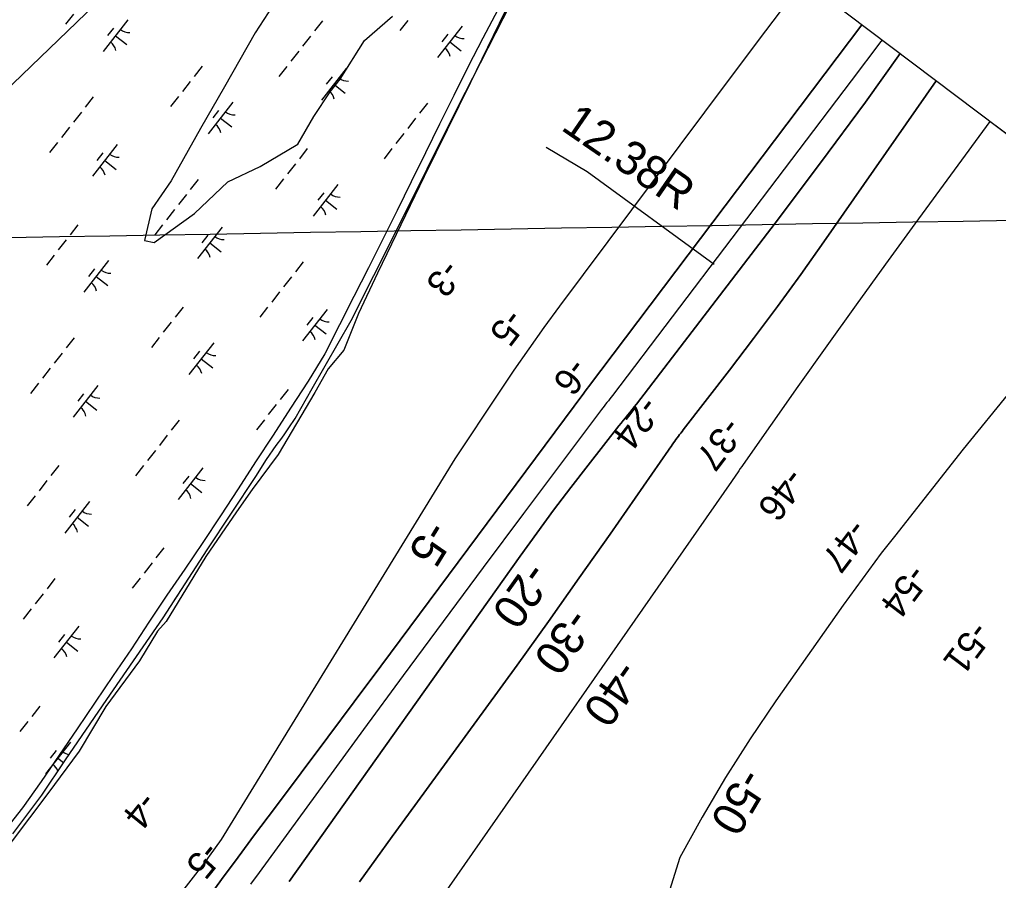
# Model space of a CAD drawing. Extents: x 3896831 to 3918110, y 171006 to 193349.
# Drawn here: x 3911133 to 3912353, y 186461 to 187534 of the extents above; entities that cross this region are included whole.
import ezdxf

# ---------------------------------------------------------------- set-up
doc = ezdxf.new("R2010")
doc.units = 0
for name, color, linetype in [('V-GRID-FRAM', 7, 'Continuous'), ('V-GRID-MAJR', 7, 'Continuous'), ('V-LEVE-TOET', 7, 'Continuous'), ('V-RIVR-EDGE', 7, 'Continuous'), ('V-RIVR-RANG', 7, 'Continuous'), ('V-RRAP-FSHR', 7, 'Continuous'), ('V-STRM-FMON', 7, 'Continuous'), ('V-TOPO-DPTH', 7, 'Continuous'), ('V-TOPO-MAJR', 7, 'Continuous'), ('V-TOPO-MAJR-IDEN', 7, 'Continuous'), ('V-TOPO-MINR', 7, 'Continuous'), ('V-TOPO-MINR-IDEN', 7, 'Continuous'), ('V-TOPO-SHOR', 7, 'Continuous'), ('V-UTIL-LINE', 7, 'Continuous'), ('V-WETL-SWMP', 7, 'Continuous')]:
    doc.layers.add(name, color=color, linetype=linetype)

msp = doc.modelspace()

# ---------------------------------------------------------------- linework, layer by layer
at = {"layer": 'V-GRID-FRAM'}
msp.add_lwpolyline([(3916044.9, 184610), (3906752.8, 172754.1), (3900055.1, 177809.8), (3909313.3, 189695.8), (3916044.9, 184610)], dxfattribs=at)
at = {"layer": 'V-GRID-MAJR'}
msp.add_spline([(3906725.4, 187187.1), (3909556.5, 187235.6), (3913560.3, 187304.5)], degree=3, dxfattribs=at)
at = {"layer": 'V-LEVE-TOET'}
msp.add_lwpolyline([(3911789.5, 187374.9), (3911840.5, 187344.6), (3911998.7, 187229.4)], dxfattribs=at)
at = {"layer": 'V-RIVR-EDGE'}
msp.add_lwpolyline([(3911759.3, 187587.7), (3911695.2, 187455.7), (3911637.6, 187338.7), (3911579.1, 187217.9), (3911555.8, 187167.7), (3911537.3, 187122.2), (3911517.7, 187098.9), (3911501, 187069.2), (3911455.5, 186992.1), (3911423, 186948.4), (3911403.4, 186920.5), (3911365.3, 186864.8), (3911316.1, 186783.9), (3911304.9, 186771.8), (3911282.6, 186734.7), (3911240.8, 186678), (3911207.4, 186622.2), (3911168.4, 186569.3), (3911100.5, 186480.1)], dxfattribs=at)
at = {"layer": 'V-RRAP-FSHR'}
msp.add_lwpolyline([(3911729.1, 187546.3), (3911710.6, 187510.8), (3911692.2, 187475.4), (3911674.3, 187439.6), (3911656.6, 187403.7), (3911639.2, 187367.8), (3911621.4, 187331.9), (3911603.7, 187296), (3911585.9, 187260.2), (3911567.9, 187224.5), (3911549.8, 187188.8), (3911531.8, 187153.5), (3911513.8, 187117.3), (3911492.8, 187083.4), (3911471, 187049.8), (3911449.1, 187016.3), (3911427.3, 186982.8), (3911405.5, 186949.3), (3911383.7, 186915.7), (3911361.6, 186882.4), (3911339.2, 186849.2), (3911316.9, 186816.7), (3911294.5, 186782.9), (3911272.8, 186749.8), (3911249.7, 186716.6), (3911227.3, 186683.5), (3911204.9, 186650.3), (3911182.5, 186617.2), (3911160.1, 186584.5), (3911136.7, 186551.6), (3911112.2, 186520.5)], dxfattribs=at)
at = {"layer": 'V-TOPO-DPTH'}
msp.add_line((3913012.1, 186901.3), (3912342.5, 187407.2), dxfattribs=at)
for points in [[(3910975.3, 185824.5), (3910982.9, 185836.6), (3910990.4, 185848.6), (3910997.8, 185860.8), (3911005, 185873.1), (3911012, 185885.5), (3911344.1, 186406.2), (3911364.5, 186434.2), (3911384.9, 186462.3), (3911405.5, 186490.2), (3911426.2, 186518), (3911451, 186551), (3911484.1, 186595.3), (3911517.2, 186639.6), (3911550.2, 186683.9), (3911583.3, 186728.3), (3911836.5, 187068.6), (3911837.2, 187069.6), (3911839.4, 187072.5), (3911840.9, 187074.5), (3911842.4, 187076.4), (3912183.1, 187527.7)], [(3912230.8, 187491.6), (3912187.4, 187431), (3912131.5, 187355.5), (3912074.9, 187280.4), (3911901.9, 187054.8), (3911899.2, 187051.3), (3911896.5, 187047.9), (3911893.8, 187044.5), (3911891, 187041.1), (3911888.3, 187037.8), (3911885.6, 187034.4), (3911882.8, 187031), (3911880.2, 187027.6), (3911841.8, 186978.7), (3911820.2, 186950.8), (3911798.8, 186922.6), (3911777.8, 186894.1), (3911757.1, 186865.4), (3911469, 186459.8)], [(3911469, 186459.8), (3911757.1, 186865.4), (3911777.8, 186894.1), (3911798.8, 186922.6), (3911820.2, 186950.8), (3911841.8, 186978.7), (3911880.2, 187027.6), (3911882.8, 187031), (3911885.6, 187034.4), (3911888.3, 187037.8), (3911891, 187041.1), (3911893.8, 187044.5), (3911896.5, 187047.9), (3911899.2, 187051.3), (3911901.9, 187054.8), (3912074.9, 187280.4), (3912131.5, 187355.5), (3912187.4, 187431), (3912230.8, 187491.6)], [(3912275.5, 187457.9), (3912135.5, 187256.9), (3912106.8, 187216.4), (3912077.8, 187176.3), (3912048.1, 187136.6), (3912018.1, 187097.2), (3911960.4, 187022.8), (3911958.9, 187020.8), (3911957.4, 187018.8), (3911955.8, 187016.8), (3911954.3, 187014.8), (3911952.8, 187012.8), (3911951.3, 187010.8), (3911949.9, 187008.7), (3911948.4, 187006.6), (3911946.7, 187004.1), (3911945.2, 187001.9), (3911943.7, 186999.7), (3911942.1, 186997.5), (3911869.1, 186892.6), (3911830.8, 186838.1), (3911792.3, 186783.7), (3911753.5, 186729.6), (3911714.4, 186675.7), (3911617.9, 186543.8), (3911597.5, 186515.7), (3911577.1, 186487.5), (3911556.9, 186459.2)], [(3911556.9, 186459.2), (3911577.1, 186487.5), (3911597.5, 186515.7), (3911617.9, 186543.8), (3911714.4, 186675.7), (3911753.5, 186729.6), (3911792.3, 186783.7), (3911830.8, 186838.1), (3911869.1, 186892.6), (3911942.1, 186997.5), (3911943.7, 186999.7), (3911945.2, 187001.9), (3911946.7, 187004.1), (3911948.4, 187006.6), (3911949.9, 187008.7), (3911951.3, 187010.8), (3911952.8, 187012.8), (3911954.3, 187014.8), (3911955.8, 187016.8), (3911957.4, 187018.8), (3911958.9, 187020.8), (3911960.4, 187022.8), (3912018.1, 187097.2), (3912048.1, 187136.6), (3912077.8, 187176.3), (3912106.8, 187216.4), (3912135.5, 187256.9), (3912275.5, 187457.9)], [(3912342.5, 187407.2), (3912249.1, 187279.6), (3912212.3, 187229.1), (3912175.7, 187178.4), (3912139.4, 187127.6), (3912103.3, 187076.6), (3912035.2, 186979.7), (3912033.3, 186977.1), (3912031.5, 186974.4), (3912029.6, 186971.7), (3912027.8, 186969), (3912025.9, 186966.3), (3912024.1, 186963.6), (3912022.2, 186960.9), (3912020.4, 186958.3), (3911636.9, 186408.5)], [(3912342.5, 187407.2), (3912249.1, 187279.6), (3912212.3, 187229.1), (3912175.7, 187178.4), (3912139.4, 187127.6), (3912103.3, 187076.6), (3912035.2, 186979.7), (3912033.3, 186977.1), (3912031.5, 186974.4), (3912029.6, 186971.7), (3912027.8, 186969), (3912025.9, 186966.3), (3912024.1, 186963.6), (3912022.2, 186960.9), (3912020.4, 186958.3), (3911636.9, 186408.5)]]:
    msp.add_lwpolyline(points, dxfattribs=at)
at = {"layer": 'V-TOPO-MAJR'}
msp.add_lwpolyline([(3912369.6, 187072.8), (3912309.2, 186998.5), (3912223.6, 186890), (3912207.2, 186868.9), (3912191.1, 186847.5), (3912175.3, 186825.9), (3912159.7, 186804.2), (3912075.9, 186684.9), (3912043.8, 186637.5), (3912013, 186589.3), (3911983.9, 186539.9), (3911956.1, 186489.8), (3911903.8, 186322.5)], dxfattribs=at)
at = {"layer": 'V-TOPO-MINR'}
for points in [[(3912110.3, 187582.7), (3912109.9, 187582.2), (3912063, 187520.2), (3912016.3, 187458.1), (3911806, 187176.9), (3911786.7, 187150.5), (3911767.7, 187123.9), (3911749.1, 187097), (3911730.8, 187069.9), (3911675.8, 186986.6), (3911384.6, 186512.1), (3911369.5, 186491.3), (3911368.2, 186489.6), (3911365.6, 186486.1), (3911364.3, 186484.4), (3911362.3, 186481.8), (3911361, 186480), (3910921.7, 185915.3), (3910911.1, 185901.5), (3910900.5, 185887.7), (3910890, 185873.8), (3910879.6, 185859.8), (3910869.3, 185845.7), (3910859.2, 185831.5)], [(3912183.1, 187527.7), (3911842.4, 187076.4), (3911840.9, 187074.5), (3911839.4, 187072.5), (3911837.2, 187069.6), (3911836.5, 187068.6), (3911583.3, 186728.3), (3911550.2, 186683.9), (3911517.2, 186639.6), (3911484.1, 186595.3), (3911451, 186551), (3911426.2, 186518), (3911405.5, 186490.2), (3911384.9, 186462.3), (3911364.5, 186434.2), (3911344.1, 186406.2), (3911012, 185885.5), (3911005, 185873.1), (3910997.8, 185860.8), (3910990.4, 185848.6), (3910982.9, 185836.6), (3910975.3, 185824.5)], [(3912208.1, 187508.8), (3912206.6, 187506.8), (3912169.7, 187457.6), (3911872.1, 187065.6), (3911870.4, 187063.4), (3911868.7, 187061.2), (3911867, 187059), (3911865.3, 187056.8), (3911863.6, 187054.6), (3911861.9, 187052.4), (3911860.2, 187050.1), (3911858.5, 187047.9), (3911761.3, 186918.4), (3911711.1, 186851.3), (3911661.1, 186784), (3911611.4, 186716.6), (3911561.9, 186649.1), (3911431.8, 186471.1), (3911421.2, 186456.4)], [(3912230.8, 187491.6), (3912187.4, 187431), (3912131.5, 187355.5), (3912074.9, 187280.4), (3911901.9, 187054.8), (3911899.2, 187051.3), (3911896.5, 187047.9), (3911893.8, 187044.5), (3911891, 187041.1), (3911888.3, 187037.8), (3911885.6, 187034.4), (3911882.8, 187031), (3911880.2, 187027.6), (3911841.8, 186978.7), (3911820.2, 186950.8), (3911798.8, 186922.6), (3911777.8, 186894.1), (3911757.1, 186865.4), (3911469, 186459.8)], [(3912275.5, 187457.9), (3912135.5, 187256.9), (3912106.8, 187216.4), (3912077.8, 187176.3), (3912048.1, 187136.6), (3912018.1, 187097.2), (3911960.4, 187022.8), (3911958.9, 187020.8), (3911957.4, 187018.8), (3911955.8, 187016.8), (3911954.3, 187014.8), (3911952.8, 187012.8), (3911951.3, 187010.8), (3911949.9, 187008.7), (3911948.4, 187006.6), (3911946.7, 187004.1), (3911945.2, 187001.9), (3911943.7, 186999.7), (3911942.1, 186997.5), (3911869.1, 186892.6), (3911830.8, 186838.1), (3911792.3, 186783.7), (3911753.5, 186729.6), (3911714.4, 186675.7), (3911617.9, 186543.8), (3911597.5, 186515.7), (3911577.1, 186487.5), (3911556.9, 186459.2)], [(3912342.5, 187407.2), (3912249.1, 187279.6), (3912212.3, 187229.1), (3912175.7, 187178.4), (3912139.4, 187127.6), (3912103.3, 187076.6), (3912035.2, 186979.7), (3912033.3, 186977.1), (3912031.5, 186974.4), (3912029.6, 186971.7), (3912027.8, 186969), (3912025.9, 186966.3), (3912024.1, 186963.6), (3912022.2, 186960.9), (3912020.4, 186958.3), (3911636.9, 186408.5)]]:
    msp.add_lwpolyline(points, dxfattribs=at)
at = {"layer": 'V-TOPO-SHOR'}
msp.add_lwpolyline([(3911459.1, 187567.9), (3911426.8, 187517.6), (3911388.6, 187450.4), (3911358.6, 187398.3), (3911322.1, 187333.3), (3911298.1, 187298.2), (3911288.7, 187258.7), (3911301.1, 187256.2), (3911351.2, 187292.5), (3911392.9, 187331.8), (3911432.9, 187350.8), (3911480, 187378.7), (3911500, 187413.4), (3911520.5, 187444.2), (3911532.7, 187459.8), (3911563.2, 187507.9), (3911597.9, 187538.3)], dxfattribs=at)
at = {"layer": 'V-UTIL-LINE'}
msp.add_lwpolyline([(3911670.5, 187980.3), (3909726.1, 186106.6), (3909690.7, 186047.7), (3909490.4, 185423.1), (3908571.2, 184256.5), (3908123.4, 183643.7), (3907157.1, 182394.6), (3906544.4, 181593.3), (3906120.1, 181051.2), (3905460.2, 180002.4), (3904670.7, 178765.1), (3903951.9, 177622.1), (3903445.2, 176832.5), (3902962, 176054.8), (3902856, 175866.2)], dxfattribs=at)
at = {"layer": 'V-WETL-SWMP'}
for p, q in [((3911679.6, 187424.8), (3911745.5, 187554.3)), ((3911200.3, 187540.8), (3911190.4, 187528.2)), ((3911268.1, 187533.7), (3911237.3, 187494.4)), ((3911250.3, 187523.5), (3911242.9, 187514.1)), ((3911510.7, 187532.5), (3911500.9, 187519.9)), ((3911510.7, 187532.5), (3911500.9, 187519.9)), ((3911617, 187533.1), (3911607.1, 187520.5)), ((3911684.8, 187526), (3911653.9, 187486.7)), ((3911252.7, 187514), (3911266.9, 187502.9)), ((3911495.9, 187513.6), (3911486, 187501)), ((3911495.9, 187513.6), (3911486, 187501)), ((3911667, 187515.8), (3911659.6, 187506.4)), ((3911669.4, 187506.3), (3911683.5, 187495.2)), ((3911481.1, 187494.7), (3911471.2, 187482.1)), ((3911481.1, 187494.7), (3911471.2, 187482.1)), ((3911360.8, 187475.9), (3911351, 187463.3)), ((3911466.3, 187475.8), (3911456.4, 187463.2)), ((3911466.3, 187475.8), (3911456.4, 187463.2)), ((3911540.4, 187473.1), (3911509.6, 187433.7)), ((3911540.4, 187473.1), (3911509.6, 187433.7)), ((3911522.6, 187462.9), (3911515.2, 187453.4)), ((3911522.6, 187462.9), (3911515.2, 187453.4)), ((3911346, 187457), (3911336.2, 187444.4)), ((3911525, 187453.4), (3911539.2, 187442.3)), ((3911525, 187453.4), (3911526.7, 187452.1)), ((3911225, 187437.6), (3911215.1, 187425)), ((3911331.2, 187438.1), (3911321.4, 187425.6)), ((3911399.1, 187431.1), (3911368.2, 187391.8)), ((3911399.1, 187431.1), (3911368.2, 187391.8)), ((3911641.6, 187429.9), (3911631.8, 187417.3)), ((3911210.2, 187418.7), (3911200.3, 187406.1)), ((3911381.3, 187420.9), (3911373.9, 187411.5)), ((3911381.3, 187420.9), (3911373.9, 187411.5)), ((3911602.9, 187271.3), (3911679.6, 187424.8)), ((3911383.6, 187411.4), (3911397.8, 187400.3)), ((3911383.6, 187411.4), (3911397.8, 187400.3)), ((3911626.8, 187411), (3911617, 187398.4)), ((3911195.4, 187399.8), (3911185.5, 187387.2)), ((3911612, 187392.1), (3911602.2, 187379.5)), ((3911180.6, 187380.9), (3911170.7, 187368.3)), ((3911254.7, 187378.2), (3911223.9, 187338.8)), ((3911236.9, 187368), (3911229.5, 187358.5)), ((3911491.8, 187373.3), (3911481.9, 187360.7)), ((3911597.2, 187373.2), (3911587.4, 187360.6)), ((3911239.3, 187358.5), (3911253.5, 187347.4)), ((3911477, 187354.4), (3911467.1, 187341.8)), ((3911355.9, 187334.9), (3911346, 187322.4)), ((3911355.9, 187334.9), (3911346, 187322.4)), ((3911462.2, 187335.5), (3911452.3, 187322.9)), ((3911530, 187328.5), (3911499.1, 187289.2)), ((3911341.1, 187316.1), (3911331.2, 187303.5)), ((3911341.1, 187316.1), (3911331.2, 187303.5)), ((3911512.2, 187318.3), (3911504.8, 187308.9)), ((3911514.5, 187308.8), (3911528.7, 187297.7)), ((3911326.3, 187297.2), (3911316.4, 187284.6)), ((3911326.3, 187297.2), (3911316.4, 187284.6)), ((3911206, 187278.4), (3911196.2, 187265.8)), ((3911311.5, 187278.3), (3911301.6, 187265.7)), ((3911311.5, 187278.3), (3911301.6, 187265.7)), ((3911385.6, 187275.5), (3911354.8, 187236.2)), ((3911546.6, 187158.9), (3911602.9, 187271.3)), ((3911191.2, 187259.5), (3911181.4, 187246.9)), ((3911367.8, 187265.3), (3911360.4, 187255.9)), ((3911370.2, 187255.9), (3911384.4, 187244.8)), ((3911176.4, 187240.6), (3911166.6, 187228)), ((3911244.2, 187233.6), (3911213.4, 187194.2)), ((3911486.8, 187232.3), (3911477, 187219.7)), ((3911226.5, 187223.4), (3911219.1, 187214)), ((3911228.8, 187213.9), (3911243, 187202.8)), ((3911472, 187213.4), (3911462.2, 187200.9)), ((3911457.2, 187194.6), (3911447.4, 187182)), ((3911337, 187175.8), (3911327.1, 187163.2)), ((3911442.4, 187175.7), (3911432.6, 187163.1)), ((3911516.6, 187172.9), (3911485.7, 187133.6)), ((3911322.2, 187156.9), (3911312.3, 187144.3)), ((3911498.8, 187162.7), (3911491.4, 187153.3)), ((3911497.7, 187074.1), (3911546.6, 187158.9)), ((3911501.1, 187153.3), (3911515.3, 187142.2)), ((3911201.1, 187137.4), (3911191.2, 187124.8)), ((3911307.3, 187138), (3911297.5, 187125.4)), ((3911375.2, 187131), (3911344.3, 187091.6)), ((3911357.4, 187120.8), (3911350, 187111.3)), ((3911186.3, 187118.5), (3911176.4, 187105.9)), ((3911359.7, 187111.3), (3911373.9, 187100.2)), ((3911171.5, 187099.7), (3911161.6, 187087.1)), ((3911156.7, 187080.8), (3911146.8, 187068.2)), ((3911230.8, 187078), (3911200, 187038.7)), ((3911467.9, 187073.2), (3911458, 187060.6)), ((3911476.7, 187036.8), (3911497.7, 187074.1)), ((3911213, 187067.8), (3911205.6, 187058.4)), ((3911215.4, 187058.3), (3911229.6, 187047.2)), ((3911453.1, 187054.3), (3911443.2, 187041.7)), ((3911332, 187034.8), (3911322.2, 187022.2)), ((3911438.3, 187035.4), (3911428.4, 187022.8)), ((3911468.8, 187025.2), (3911476.7, 187036.8)), ((3911463.8, 187017.7), (3911468.8, 187025.2)), ((3911317.2, 187015.9), (3911307.4, 187003.3)), ((3911452.8, 187003.4), (3911459.9, 187012.4)), ((3911459.9, 187012.4), (3911463.8, 187017.7)), ((3911440.8, 186985.6), (3911452.8, 187003.4)), ((3911302.4, 186997), (3911292.6, 186984.4)), ((3911182.2, 186978.3), (3911172.3, 186965.7)), ((3911287.6, 186978.2), (3911277.7, 186965.6)), ((3911361.7, 186975.4), (3911330.9, 186936.1)), ((3911427.8, 186964.7), (3911440.8, 186985.6)), ((3911344, 186965.2), (3911336.6, 186955.8)), ((3911367, 186873), (3911427.8, 186964.7)), ((3911167.3, 186959.4), (3911157.5, 186946.8)), ((3911346.3, 186955.7), (3911360.5, 186944.6)), ((3911152.5, 186940.5), (3911142.7, 186927.9)), ((3911220.4, 186933.5), (3911189.5, 186894.1)), ((3911202.6, 186923.3), (3911195.2, 186913.8)), ((3911204.9, 186913.8), (3911219.1, 186902.7)), ((3911313.1, 186875.7), (3911303.2, 186863.1)), ((3911312, 186788.6), (3911367, 186873)), ((3911298.3, 186856.8), (3911288.4, 186844.2)), ((3911177.2, 186837.3), (3911167.4, 186824.7)), ((3911283.5, 186837.9), (3911273.6, 186825.3)), ((3911162.4, 186818.4), (3911152.5, 186805.8)), ((3911330.2, 186816.4), (3911326.1, 186811.2)), ((3911147.6, 186799.5), (3911137.7, 186786.9)), ((3911241.8, 186686.5), (3911312, 186788.6)), ((3911206.9, 186777.9), (3911176.1, 186738.5)), ((3911189.1, 186767.7), (3911181.7, 186758.3)), ((3911191.5, 186758.2), (3911205.7, 186747.1)), ((3911190.5, 186611.6), (3911241.8, 186686.5)), ((3911158.3, 186678.2), (3911148.4, 186665.6)), ((3911143.5, 186659.3), (3911133.6, 186646.7)), ((3911196.5, 186633.3), (3911165.6, 186594)), ((3911178.7, 186623.1), (3911171.3, 186613.7)), ((3911161, 186567.4), (3911190.5, 186611.6)), ((3911181, 186613.7), (3911188.1, 186608.1)), ((3911125, 186519.1), (3911161, 186567.4))]:
    msp.add_line(p, q, dxfattribs=at)
msp.add_lwpolyline([(3911459.1, 187567.9), (3911426.8, 187517.6), (3911388.6, 187450.4), (3911358.6, 187398.3), (3911322.1, 187333.3), (3911298.1, 187298.2), (3911288.7, 187258.7), (3911301.1, 187256.2), (3911351.2, 187292.5), (3911392.9, 187331.8), (3911432.9, 187350.8), (3911480, 187378.7), (3911500, 187413.4), (3911520.5, 187444.2), (3911532.7, 187459.8), (3911563.2, 187507.9), (3911597.9, 187538.3)], dxfattribs=at)
for centre, start, end in [((3911269.9, 187535.6), 231.1403, 272.6839), ((3911686.6, 187527.9), 231.1403, 272.6839), ((3911235.9, 187492.2), 11.1403, 52.6839), ((3911652.5, 187484.5), 11.1403, 52.6839), ((3911542.2, 187475), 231.1403, 272.6839), ((3911542.2, 187475), 231.1403, 237.9349), ((3911508.2, 187431.5), 11.1403, 52.6839), ((3911508.2, 187431.5), 45.7735, 52.6839), ((3911400.9, 187433), 231.1403, 272.6839), ((3911400.9, 187433), 231.1403, 272.6839), ((3911366.8, 187389.5), 11.1403, 52.6839), ((3911366.8, 187389.5), 11.1403, 52.6839), ((3911256.5, 187380.1), 231.1403, 272.6839), ((3911222.4, 187336.6), 11.1403, 52.6839), ((3911531.8, 187330.4), 231.1403, 272.6839), ((3911497.7, 187286.9), 11.1403, 52.6839), ((3911387.4, 187277.5), 231.1403, 272.6839), ((3911353.4, 187234), 11.1403, 52.6839), ((3911246, 187235.5), 231.1403, 272.6839), ((3911212, 187192), 11.1403, 52.6839), ((3911518.4, 187174.9), 231.1403, 272.6839), ((3911484.3, 187131.4), 11.1403, 52.6839), ((3911377, 187132.9), 231.1403, 272.6839), ((3911342.9, 187089.4), 11.1403, 52.6839), ((3911232.6, 187079.9), 231.1403, 272.6839), ((3911198.6, 187036.5), 11.1403, 52.6839), ((3911363.6, 186977.3), 231.1403, 272.6839), ((3911329.5, 186933.9), 11.1403, 52.6839), ((3911222.2, 186935.4), 231.1403, 272.6839), ((3911188.1, 186891.9), 11.1403, 52.6839), ((3911208.7, 186779.8), 231.1403, 272.6839), ((3911174.7, 186736.3), 11.1403, 52.6839), ((3911198.3, 186635.3), 231.1403, 258.8095), ((3911164.2, 186591.8), 18.2391, 52.6839)]:
    msp.add_arc(centre, 17.6, start, end, dxfattribs=at)

# ---------------------------------------------------------------- texts
at = {"layer": 'V-RIVR-RANG'}
for s, rotation, p in [('-3', 232.6583, (3911662.3, 187236.9)), ('-5', 232.6583, (3911741.4, 187175.8)), ('-6', 232.6583, (3911820.6, 187114.7)), ('-24', 232.6583, (3911909.9, 187066.9)), ('-37', 232.7959, (3912012.9, 187040.6)), ('-46', 232.7959, (3912090.7, 186977.6)), ('-47', 232.7959, (3912169.5, 186913.6)), ('-54', 232.7959, (3912243.7, 186857.2)), ('-51', 232.7959, (3912321.8, 186786.3)), ('-4', 231.0783, (3911285.2, 186573.9)), ('-5', 231.0783, (3911363.7, 186511.9))]:
    msp.add_text(s, height=33.5, rotation=rotation, dxfattribs=at).set_placement(p)
at = {"layer": 'V-STRM-FMON'}
msp.add_text('12.38R', height=42, rotation=325.4446, dxfattribs=at).set_placement((3911806.5, 187397.5))
at = {"layer": 'V-TOPO-MAJR-IDEN'}
msp.add_text('-50', height=41.5, rotation=239.5101, dxfattribs=at).set_placement((3912033.5, 186603.8))
at = {"layer": 'V-TOPO-MINR-IDEN'}
for s, rotation, p in [('-5', 238.4654, (3911642.3, 186912.1)), ('-20', 234.613, (3911766.6, 186860.7)), ('-30', 234.2945, (3911818.9, 186802.9)), ('-40', 235.106, (3911879.6, 186738.3))]:
    msp.add_text(s, height=41.5, rotation=rotation, dxfattribs=at).set_placement(p)

doc.saveas('drawing.dxf')
